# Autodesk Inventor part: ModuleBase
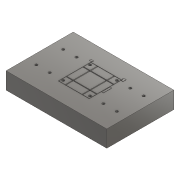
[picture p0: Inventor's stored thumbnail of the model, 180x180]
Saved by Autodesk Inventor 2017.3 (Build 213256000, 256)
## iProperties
Part Number: ModuleBase
Material: ステンレス鋼
Document SubType Name: Modeling
Designer: kyushu-hep
Density: 8 g/cm^3
Appearance: 半つや出し
Mass: 96.9479 g
Surface Area: 172.882 cm^2
Volume: 104.245 cm^3
Author: kyushu-hep
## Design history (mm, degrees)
sketch "スケッチ1"
  geometry: L1 (-60, 40)-(60, 40); L2 (60, 40)-(60, -40); L3 (60, -40)-(-60, -40); L4 (-60, -40)-(-60, 40); 1 further point
  constraints: 8 end point, 2 parallel, 1 horizontal, 1 perpendicular
  dimensions: "d0" = 120 distance of L2.end L3.end; "d1" = 80 distance of L1.end L2.end; "d22" = 40 distance from line of point (0, 0) L3; "d23" = 60 distance from line of L2 point (0, 0)
extrude "押し出し1" new body sketch "スケッチ1" distance "d2" = 20; taper "d3" = 0 deg
sketch "スケッチ4"
  geometry: L1 (17.855, 22.225)-(17.855, 20.225); L2 (17.855, 20.225)-(19.055, 20.225); L3 (19.055, 20.225)-(19.055, 18.225); L4 (19.055, 18.225)-(21.055, 18.225); L5 (21.055, 18.225)-(21.055, 22.225); L6 (21.055, 22.225)-(17.855, 22.225); L7 (21.055, 5)-(21.055, -5); L8 (21.055, -5)-(19.055, -5); L9 (19.055, -5)-(19.055, 5); L10 (19.055, 5)-(21.055, 5); L11 (-60, -40)-(60, -40) reference; L12 (-60, 40)-(-60, -40) reference; L13 (-21.055, 22.225)-(-17.855, 22.225); L14 (-17.855, 22.225)-(-17.855, 20.225); L15 (-17.855, 20.225)-(-21.055, 20.225); L16 (-21.055, 20.225)-(-21.055, 22.225); 1 further point
  constraints: 28 end point, 8 perpendicular, 4 point on line, 2 parallel, 1 collinear, 1 horizontal, 1 vertical
  dimensions: "d12" = 2 distance of L1.start L1.end; "d13" = 1.2 distance of L1.end L2.end; "d14" = 2 distance of L2.end L3.end; "d15" = 2 distance of L3.end L4.end; "d16" = 10 distance of L7.start L7.end; "d24" = 19.055 distance from line of L9 point (0, 0); "d25" = 22.225 distance from line of point (0, 0) L6; "d28" = 17.855 distance from line of point (0, 0) L14
extrude "押し出し4" join sketch "スケッチ4" distance "d29" = 0.3; taper "d30" = 0 deg
sketch "スケッチ6"
  geometry: L1 (20, 20)-(-20, 20); L2 (-20, 20)-(-20, -20); L3 (-20, -20)-(20, -20); L4 (20, -20)-(20, 20); L5 (20, 20)-(-20, -20); L6 (-20, 20)-(20, -20); C1 r 1.5 at (-48, -16); C2 r 1.5 at (-48, 16); C3 r 1.5 at (-32, -16); C4 r 1.5 at (-32, 16); C5 r 1.5 at (-16, -16); C6 r 1.5 at (-16, 16); C7 r 1.5 at (0, -16); C8 r 1.5 at (0, 16); C9 r 1.5 at (16, -16); C10 r 1.5 at (16, 16); C11 r 1.5 at (32, -16); C12 r 1.5 at (32, 16); C13 r 1.5 at (48, -16); C14 r 1.5 at (48, 16); 1 further point
  constraints: 14 centre point, 12 end point, 2 horizontal, 2 midpoint, 2 parallel, 1 perpendicular, 1 vertical, 26 other
  dimensions: "d41" = 3 diameter of C1; "d42" = 48 horizontal distance of point (0, 0) C1.centre; "d43" = 16 vertical distance of point (0, 0) C1.centre; "d44" = 40 distance of L3.end L2.end; "d45" = 40 distance of L2.end L1.end; "d48" = 32 distance of C1.centre C2.centre; "d51" = 16 distance of C1.centre C3.centre
sketch "スケッチ7"
  geometry: C1 r 0.5 at (-10, 10); C2 r 0.5 at (10, 10); C3 r 0.5 at (-10, -10); C4 r 0.5 at (10, -10); 1 further point
  constraints: 4 centre point
  dimensions: "d58" = 1 diameter of C1; "d59" = 10 horizontal distance of point (0, 0) C1.centre; "d60" = 10 horizontal distance of point (0, 0) C1.centre; "d61" = 1 diameter of C2; "d62" = 10 horizontal distance of point (0, 0) C2.centre; "d63" = 1 diameter of C3; "d64" = 10 horizontal distance of point (0, 0) C3.centre; "d65" = 1 diameter of C4
extrude "押し出し9" cut sketch "スケッチ7" distance "d66" = 10; taper "d67" = 0 deg
sketch "スケッチ9"
  geometry: L1 (18.5, -19.5)-(-18.5, -19.5); L2 (-18.5, -19.5)-(-18.5, 19.5); L3 (-18.5, 19.5)-(18.5, 19.5); L4 (18.5, 19.5)-(18.5, -19.5); L5 (18.5, -19.5)-(-18.5, 19.5); L6 (-18.5, -19.5)-(18.5, 19.5); L7 (-10.5, 10.5)-(-18, 10.5); L8 (-18, 10.5)-(-18, 19); L9 (-18, 19)-(-10.5, 19); L10 (-10.5, 19)-(-10.5, 10.5); L11 (-10.5, 10.5)-(-18, 19); L12 (-18, 10.5)-(-10.5, 19); L13 (18, 10.5)-(10.5, 10.5); L14 (10.5, 10.5)-(10.5, 19); L15 (10.5, 19)-(18, 19); L16 (18, 19)-(18, 10.5); L17 (-9.5, 19)-(9.5, 19); L18 (9.5, 19)-(9.5, 10.5); L19 (9.5, 10.5)-(-9.5, 10.5); L20 (-9.5, 10.5)-(-9.5, 19); L21 (-18, 9.5)-(-10.5, 9.5); L22 (-10.5, 9.5)-(-10.5, -9.5); L23 (-10.5, -9.5)-(-18, -9.5); L24 (-18, -9.5)-(-18, 9.5); L25 (-18, -10.5)-(-10.5, -10.5); L26 (-10.5, -10.5)-(-10.5, -19); L27 (-10.5, -19)-(-18, -19); L28 (-18, -19)-(-18, -10.5); L29 (-9.5, 9.5)-(9.5, 9.5); L30 (9.5, 9.5)-(9.5, -9.5); L31 (9.5, -9.5)-(-9.5, -9.5); L32 (-9.5, -9.5)-(-9.5, 9.5); L33 (10.5, 9.5)-(18, 9.5); L34 (18, 9.5)-(18, -9.5); L35 (18, -9.5)-(10.5, -9.5); L36 (10.5, -9.5)-(10.5, 9.5); L37 (-9.5, -10.5)-(9.5, -10.5); L38 (9.5, -10.5)-(9.5, -19); L39 (9.5, -19)-(-9.5, -19); L40 (-9.5, -19)-(-9.5, -10.5); L41 (10.5, -10.5)-(18, -10.5); L42 (18, -10.5)-(18, -19); L43 (18, -19)-(10.5, -19); L44 (10.5, -19)-(10.5, -10.5); 2 further points
  constraints: 88 end point, 20 parallel, 19 collinear, 10 horizontal, 10 perpendicular, 4 midpoint, 4 point on line
  dimensions: "d78" = 37 distance of L2.end L3.end; "d79" = 39 distance of L1.end L2.end; "d80" = 7.5 distance of L8.end L9.end; "d81" = 0.5 distance between parallel lines of L3 L9; "d82" = 0.5 distance between parallel lines of L2 L8; "d83" = 8.5 distance of L7.end L8.end; "d88" = 19 distance of L18.end L19.end; "d89" = 8.5 distance of L17.end L18.end; "d90" = 1 distance between parallel lines of L10 L20; "d92" = 19 distance of L21.end L22.end; "d93" = 1 distance between parallel lines of L21 L7; "d94" = 8.5 distance of L25.end L26.end; "d95" = 1 distance between parallel lines of L25 L23; "d96" = 8.5 distance of L13.end L14.end; "d97" = 1 distance between parallel lines of L14 L18
extrude "押し出し11" cut sketch "スケッチ9" distance "d98" = 1; taper "d99" = 0 deg
extrude "押し出し12" cut sketch "スケッチ6" distance "d100" = 20; taper "d101" = 0 deg
node "ソリッド1"
